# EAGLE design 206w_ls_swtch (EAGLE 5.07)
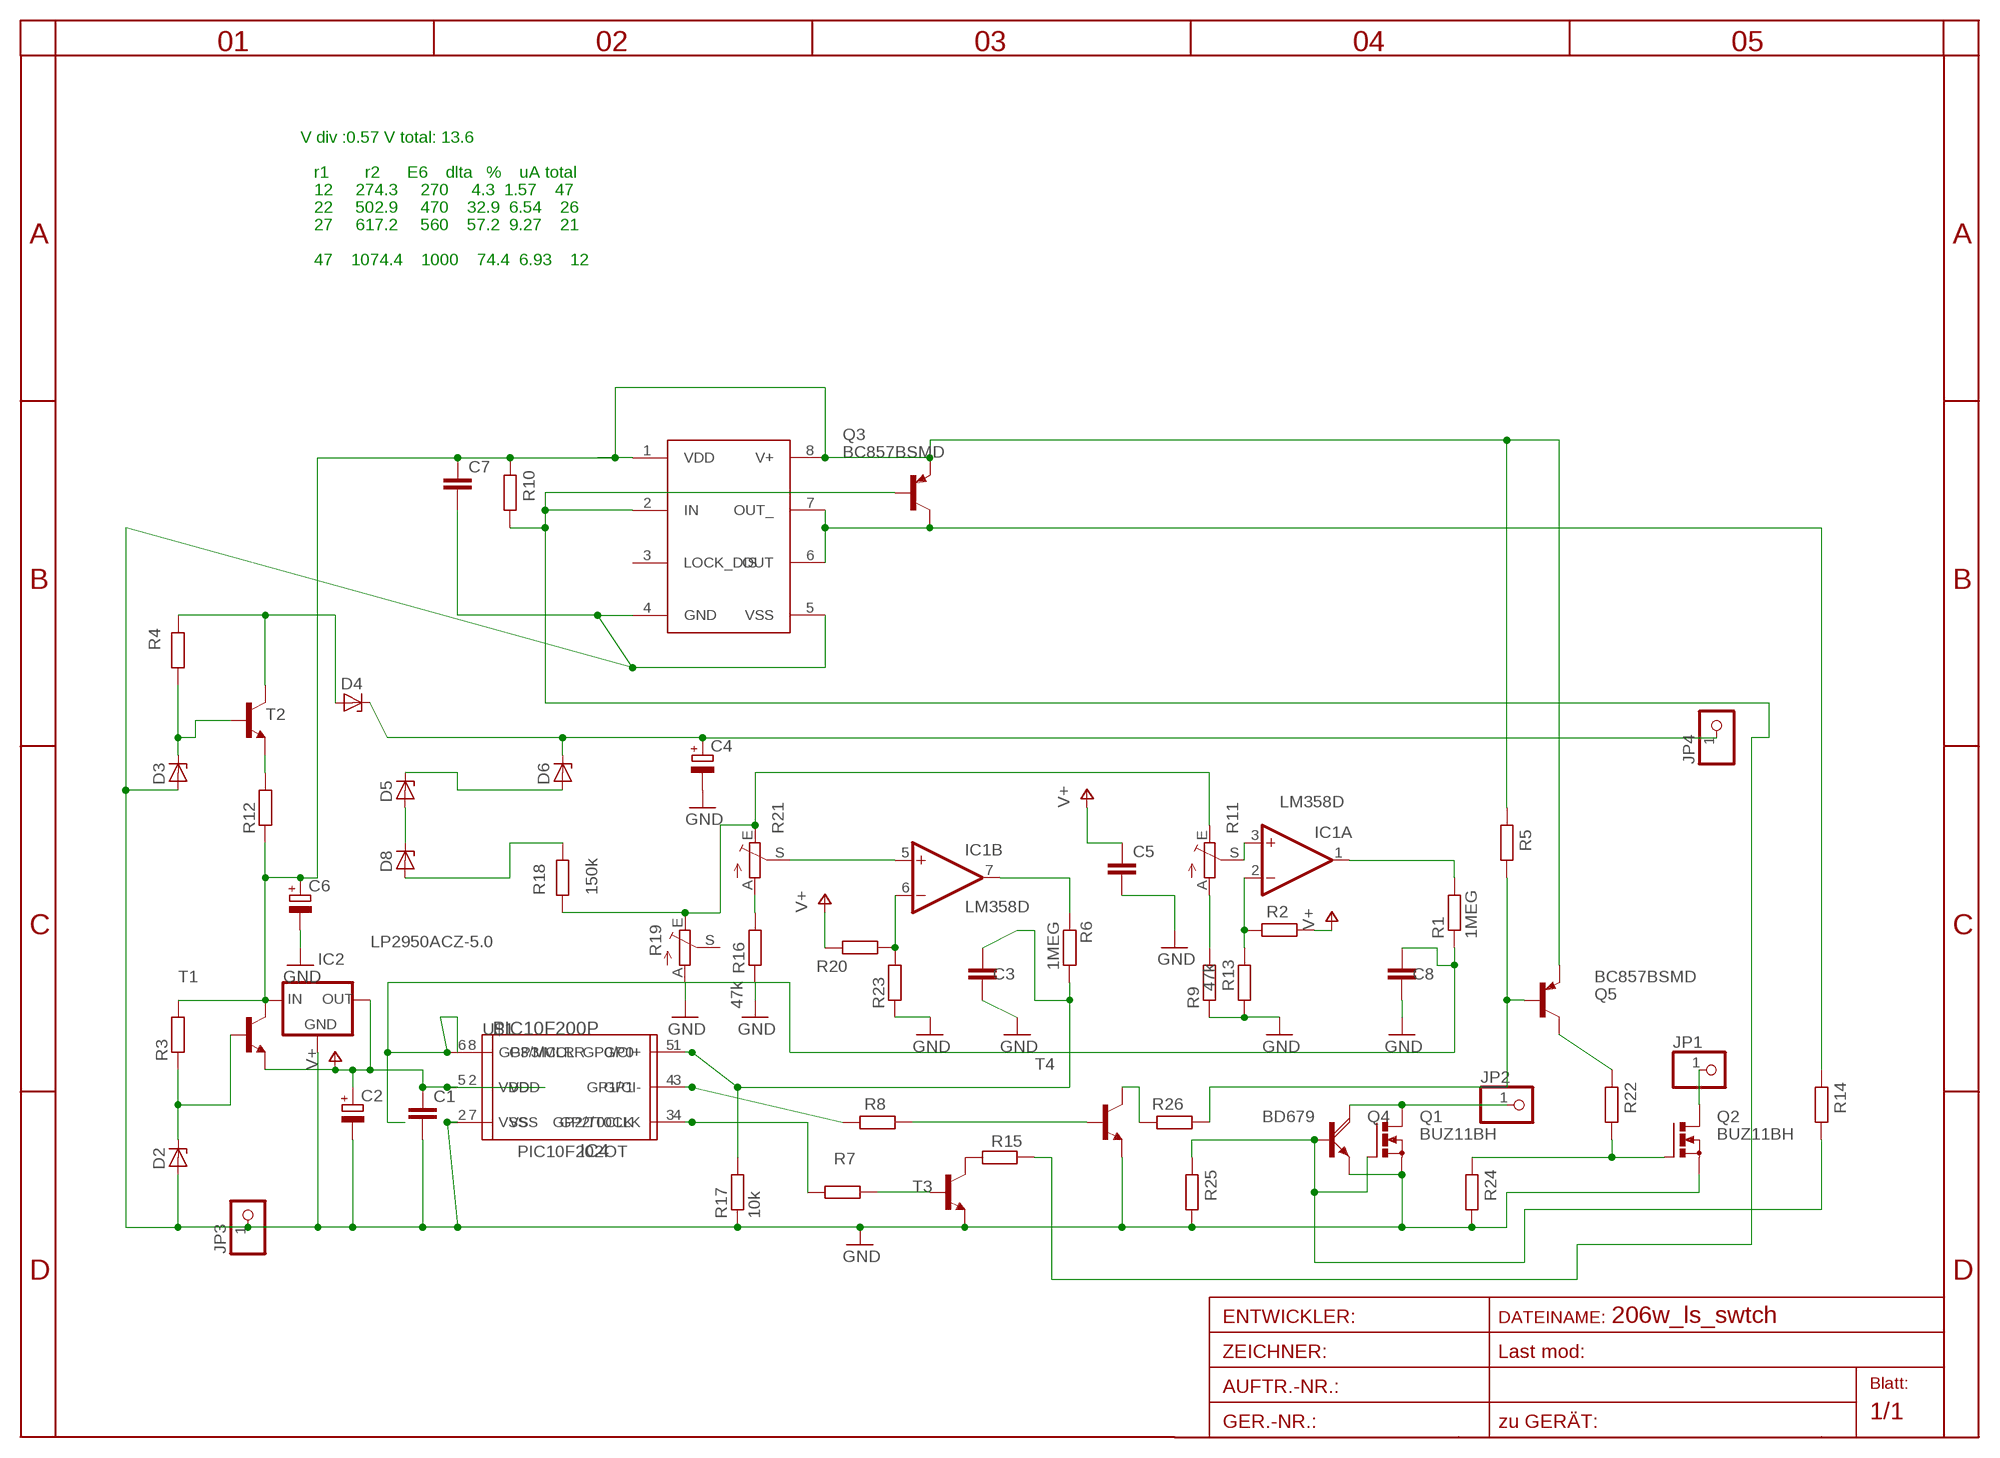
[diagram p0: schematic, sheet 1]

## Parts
C1  C-EUC1206  [C1206]
C2  CPOL-EUSANYO_SMD_E12  [SANYO-OSCON_SMD_E12]
C3  C-EUC1206  [C1206]
C4  CPOL-EUE5-8.5  [E5-8,5]
C5  C-EUC1206  [C1206]
C6  CPOL-EUSANYO_SMD_E12  [SANYO-OSCON_SMD_E12]
C7  C-EUC1206  [C1206]
C8  C-EUC1206  [C1206]
D2  ZENER-DIODESOD80C  [SOD80C]
D3  ZENER-DIODESMB  [SMB]
D4  ZENER-DIODESMB  [SMB]
D5  ZENER-DIODESMB  [SMB]
D6  ZENER-DIODESMB  [SMB]
D8  ZENER-DIODESMB  [SMB]
IC1  LM358D  [SO08]
IC2  LP2950ACZ-5.0  [TO92]
IC3  TC4432X  [SO-08]
IC4  PIC10F200P  [DIL8]
JP1  PINHD-1X11MM6  [1X1MM8]
JP2  PINHD-1X11MM6  [1X1MM8]
JP3  PINHD-1X11MM6  [1X1MM8]
JP4  PINHD-1X11MM6  [1X1MM8]
Q1  BUZ11BH  [TO220BH]
Q2  BUZ11BH  [TO220BH]
Q3  BC857BSMD  [SOT23-BEC]
Q4  BD679  [TO126AV]
Q5  BC857BSMD  [SOT23-BEC]
R1  1MEG  R-EU_R1206  [R1206]
R2  R-EU_R0805  [R0805]
R3  R-EU_R0805  [R0805]
R4  R-EU_R0805  [R0805]
R5  R-EU_R0805  [R0805]
R6  1MEG  R-EU_R1206  [R1206]
R7  R-EU_R0805  [R0805]
R8  R-EU_R0805  [R0805]
R9  47k  R-EU_R0805  [R0805]
R10  R-EU_R0805  [R0805]
R11  TRIM_EU-CA6V  [CA6V]
R12  R-EU_R0805  [R0805]
R13  R-EU_R1206  [R1206]
R14  R-EU_R0805  [R0805]
R15  R-EU_R0805  [R0805]
R16  47k  R-EU_R0805  [R0805]
R17  10k  R-EU_R0805  [R0805]
R18  150k  R-EU_R1206  [R1206]
R19  TRIM_EU-CA6V  [CA6V]
R20  R-EU_R1206  [R1206]
R21  TRIM_EU-CA6V  [CA6V]
R22  R-EU_R0805  [R0805]
R23  R-EU_R1206  [R1206]
R24  R-EU_R0805  [R0805]
R25  R-EU_R0805  [R0805]
R26  R-EU_R0805  [R0805]
T1  BC846BLT1-NPN-SOT23-BEC  [SOT23-BEC]
T2  BC846BLT1-NPN-SOT23-BEC  [SOT23-BEC]
T3  BC846BLT1-NPN-SOT23-BEC  [SOT23-BEC]
T4  BC846BLT1-NPN-SOT23-BEC  [SOT23-BEC]
U$1  PIC10F202OT  [SOT23-6]

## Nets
BB: IC3.2(IN) Q3.B R10.1 R15.2
GND: C1.2 C2.- C3.2 C4.- C5.2 C6.- C7.2 C8.2 D2.A D3.A IC2.2(GND) IC3.4(GND) IC3.5(VSS) IC4.7(VSS) JP3.1 Q1.S Q2.S Q4.E R9.1 R13.1 R16.1 R17.1 R19.A R23.1 R24.1 R25.1 T3.E T4.E U$1.2(VSS)
HOTSPOT: JP2.1 Q1.D Q4.C
N$1: IC1.5(B:+IN) R21.S
N$2: C8.1 IC4.8(GP3/MCLR) R1.1 U$1.6(GP3/MCLR)
N$3: Q1.G Q4.B R14.1 R25.2
N$4: R11.E R18.1 R19.E R21.E
N$5: R26.2 T4.C
N$6: D2.C R3.1 T1.B
N$7: R9.2 R11.A
N$8: IC1.3(A:+IN) R11.S
N$9: IC4.3(GP2/T0CLK) R7.1 U$1.4(GP2/T0CLK)
N$10: D5.C D6.A
N$11: IC3.6(OUT) IC3.7(OUT_) Q3.C R14.2
N$12: D3.C R4.1 T2.B
N$13: R8.1 T4.B
N$14: C3.1 IC4.5(GP0) R6.2 R17.2 U$1.1(GP0/CI+)
N$15: IC1.2(A:-IN) R2.2 R13.2
N$17: D5.A D8.C
N$19: D8.A R18.2
N$21: D4.A R4.2 T2.C
N$22: R12.2 T2.E
N$23: R16.2 R21.A
N$24: IC1.6(B:-IN) R20.2 R23.2
N$25: IC4.4(GP1) R8.2 U$1.3(GP1/CI-)
N$26: R7.2 T3.B
N$27: IC1.7(B:OUT) R6.1
N$28: Q5.C R22.2
N$29: Q2.G R22.1 R24.2
N$30: Q5.B R5.1 R26.1
N$31: R15.1 T3.C
N$33: IC1.1(A:OUT) R1.2
OUT2: JP1.1 Q2.D
V60: C4.+ D4.C D6.C JP4.1
V+: C1.1 C2.+ C5.1 IC2.1(OUT) IC4.2(VDD) R2.1 R20.1 T1.E U$1.5(VDD)
VCC: C6.+ C7.1 IC2.3(IN) IC3.1(VDD) IC3.8(V+) Q3.E Q5.E R3.2 R5.2 R10.2 R12.1 T1.C
Unconnected: IC3.3(LOCK_DIS) R19.S

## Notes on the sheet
- V div :0.57 V total: 13.6
- r1        r2      E6    dlta   %    uA total
- 12     274.3     270     4.3  1.57    47
- 22     502.9     470    32.9  6.54    26
- 27     617.2     560    57.2  9.27    21
- 47    1074.4    1000    74.4  6.93    12

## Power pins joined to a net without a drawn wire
GND: IC1.4(P:V-)
V+: IC1.8(P:V+)

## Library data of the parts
C1 C3 C5 C7 C8 = rcl:C-EU: CAPACITOR, European symbol
C2 C4 C6 = rcl:CPOL-EU: POLARIZED CAPACITOR, European symbol
D2-D6 D8 = diode-1:ZENER-DIODE: Z-Diode
IC1 = linear4:LM358: OP AMP
IC2 = v-reg:LP2950?*: Source: http://cache.national.com/ds/LP/LP2950.pdf
IC3 = microchip:TC4432
IC4 = microchip-5:PIC10F20*: uPC nW 0,25/0,5k Program Flash memory
JP1-JP4 = pinhead:PINHD-1X1: PIN HEADER
Q1 Q2 = transistor-power:BUZ11: N-CHANNEL MOS FET
Q3 Q5 = transistor-pnp:BC857*: PNP Transistror
Q4 = transistor-power:BD679: NPN DARLINGTON TRANSISTOR
R1-R6 R8-R10 R12 R14-R16 R20 R22 R24-R26 = rcl:R-EU_: RESISTOR, European symbol
R7 R13 R17 R18 R23 = rcl-2:R-EU_: RESISTOR, European symbol
R11 R19 R21 = pot:TRIM_EU-: POTENTIOMETER
T1-T4 = transistor-neu-to92:*-NPN-: NPN Transistror
U$1 = microchip-5:PIC10F2*: uPC nW 0,25/0,5k Program Flash memory Comparator

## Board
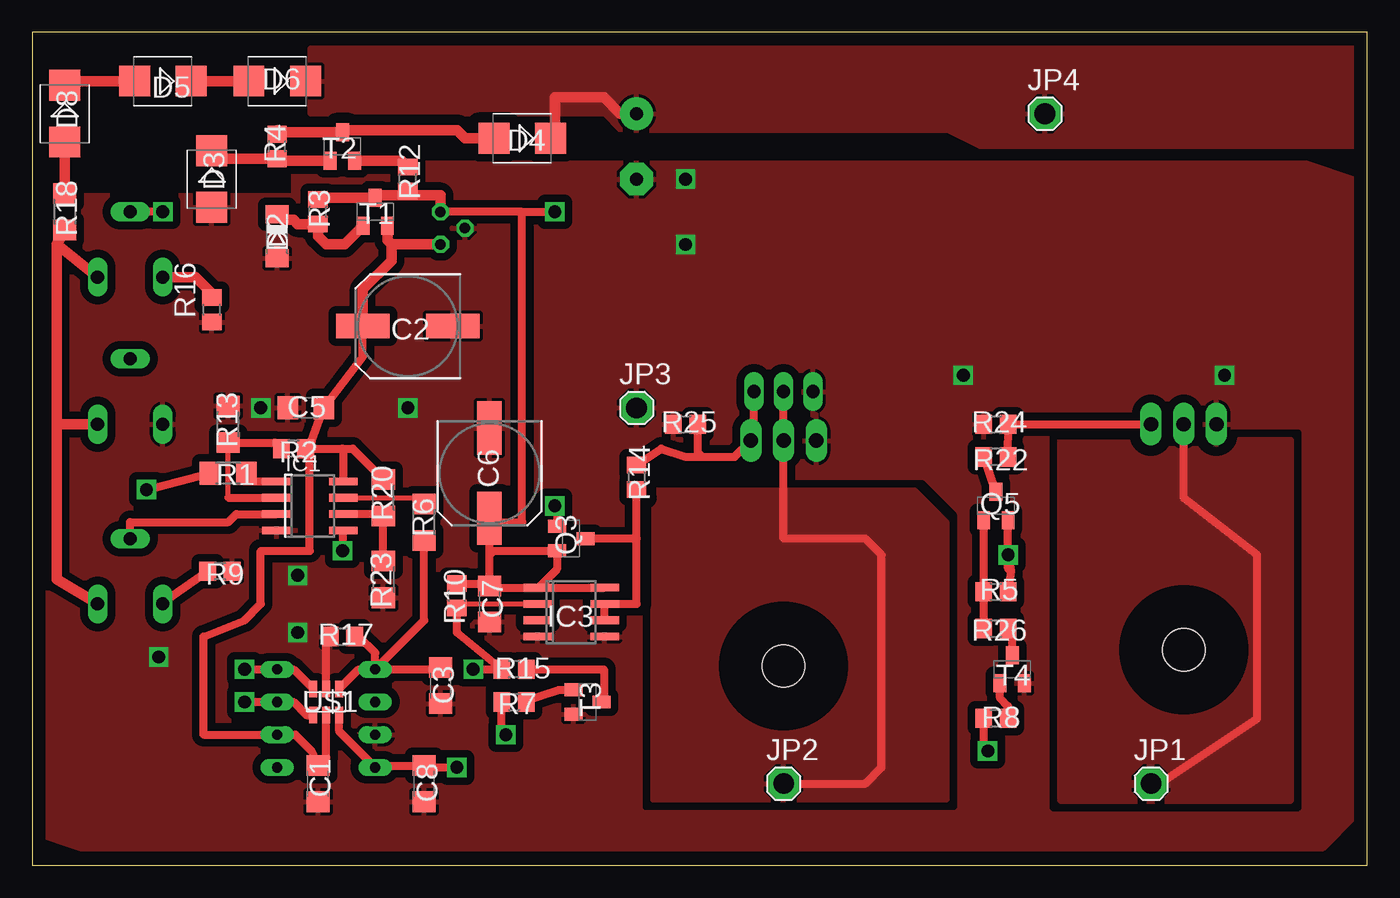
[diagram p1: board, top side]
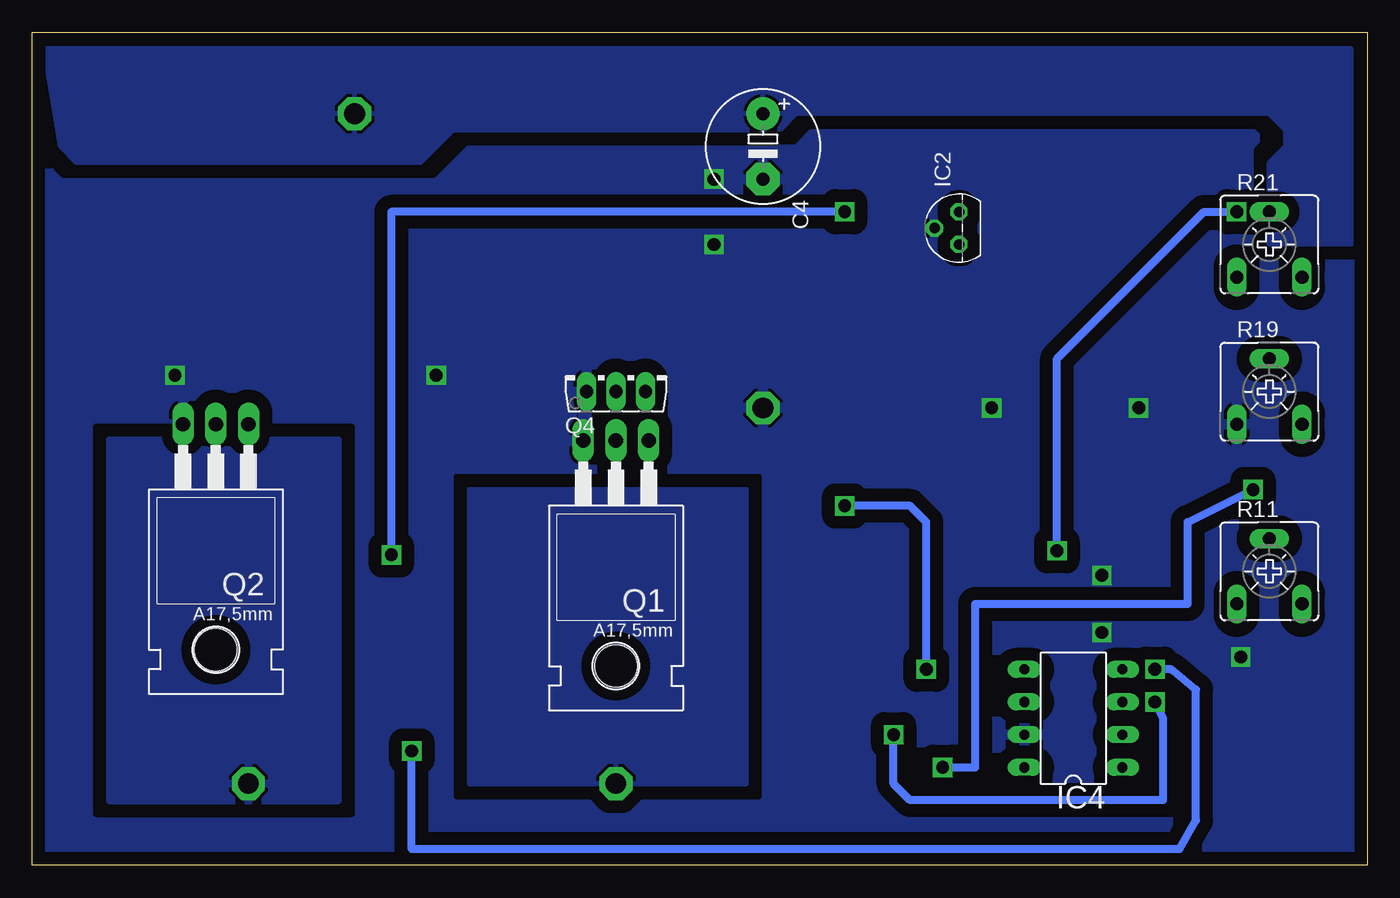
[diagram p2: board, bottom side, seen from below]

Size 103.81 x 64.76 mm. Coordinates in mm from the lower left corner, seen from the top.
Outline: 0,0 103.81,0 103.81,64.76 0,64.76 0,0
Copper layers (1*16): Top 0.035mm / dielectric 1.5mm / Bottom 0.035mm
Design rules "default": minimum track width 10mil, minimum drill 24mil, track to track 8mil, track to pad 8mil, pad to pad 8mil, via to via 8mil, smd to smd 8mil, copper to edge 40mil, drill to drill 8mil, minimum pad ring 10mil, minimum via ring 8mil, stop-mask expansion 4mil, vias tented up to drill 0mil, thermal gap 10mil

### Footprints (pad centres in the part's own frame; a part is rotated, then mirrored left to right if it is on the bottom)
C1206 = smd 1.6 x 1.8: 1 -1.4,0; 2 1.4,0
SANYO-OSCON_SMD_E12 = smd 4.15 x 1.9: + 3.5,0; - -3.5,0
E5-8,5 = drill 1.016 pad 2.54 round: + -2.54,0 | drill 1.016 pad 2.54 octagon: - 2.54,0
SOD80C = smd 1.4 x 1.8: A 1.7,0; C -1.7,0
SMB = smd 2.4 x 2.4: A 2.2,0; C -2.2,0
SO08 = smd 0.6 x 2.2: 1 -1.905,-2.6; 2 -0.635,-2.6; 3 0.635,-2.6; 4 1.905,-2.6; 5 1.905,2.6; 6 0.635,2.6; 7 -0.635,2.6; 8 -1.905,2.6
TO92 = drill 0.813 octagon: 1 -1.27,0; 2 0,1.905; 3 1.27,0
SO-08 = smd 0.6 x 2.2: 1 -1.905,-2.6; 2 -0.635,-2.6; 3 0.635,-2.6; 4 1.905,-2.6; 5 1.905,2.6; 6 0.635,2.6; 7 -0.635,2.6; 8 -1.905,2.6
DIL8 = drill 0.8 long: 1 -3.81,-3.81; 2 -1.27,-3.81; 3 1.27,-3.81; 4 3.81,-3.81; 5 3.81,3.81; 6 1.27,3.81; 7 -1.27,3.81; 8 -3.81,3.81
1X1MM8 = drill 1.6 pad 2.54 octagon: 1 0,0
TO220BH = drill 1.118 long: D 0,-6.35; G -2.54,-6.35; S 2.54,-6.35 | hole 3.302: 0,11.176
SOT23-BEC = smd 1 x 1.4: B -0.95,-1.1; C 0,1.1; E 0.95,-1.1
TO126AV = drill 1.016 long: B 2.286,-1.27; C 0,-1.27; E -2.286,-1.27
R1206 = smd 1.6 x 1.803: 1 -1.422,0; 2 1.422,0
R0805 = smd 1.3 x 1.5: 1 -0.95,0; 2 0.95,0
CA6V = drill 1.016 long: A -2.54,-2.54; E 2.54,-2.54; S 0,2.54
SOT23-6 = smd 0.635 x 1.27: 1 -1.016,-1.016; 2 0,-1.016; 3 1.016,-1.016; 4 1.016,1.016; 5 0,1.016; 6 -1.016,1.016

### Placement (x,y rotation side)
C1  22.23,6.35 270 top
C2  29.21,41.91 180 top
C3  31.75,13.97 270 top
C4  46.99,55.88 270 bottom
C5  21.27,35.56 180 top
C6  35.56,30.48 270 top
C7  35.56,20.32 270 top
C8  30.48,6.35 270 top
D2  19.05,48.9 270 top
D3  13.97,53.34 270 top
D4  38.1,56.52 180 top
D5  10.16,60.96 180 top
D6  19.05,60.96 180 top
D8  2.54,58.42 270 top
IC1  21.59,27.94 270 top
IC2  31.75,49.53 90 bottom
IC3  41.91,19.68 270 top
IC4  22.86,11.43 90 bottom
JP1  87,6.35 0 top
JP2  58.42,6.35 0 top
JP3  46.99,35.56 0 top
JP4  78.74,58.42 0 top
Q1  58.42,26.67 180 bottom
Q2  89.53,27.94 180 bottom
Q3  41.91,25.4 270 top
Q4  58.42,38.1 0 bottom
Q5  74.93,27.94 0 top
R1  15.24,30.48 0 top
R2  20.32,32.38 180 top
R3  22.23,50.8 90 top
R4  19.05,55.88 90 top
R5  74.93,21.27 0 top
R6  30.48,26.67 270 top
R7  37.47,12.7 0 top
R8  74.93,11.43 180 top
R9  14.61,22.86 180 top
R10  33.02,20.95 90 top
R11  7.62,22.86 0 bottom
R12  29.21,53.34 90 top
R13  15.24,34.29 270 top
R14  46.99,30.16 270 top
R15  37.47,15.24 180 top
R16  13.97,43.18 90 top
R17  24.13,17.78 0 top
R18  2.54,50.8 90 top
R19  7.62,36.83 0 bottom
R20  27.3,28.57 270 top
R21  7.62,48.26 0 bottom
R22  74.93,31.75 180 top
R23  27.3,22.23 90 top
R24  74.93,34.29 0 top
R25  50.8,34.29 0 top
R26  74.93,18.41 0 top
T1  26.67,50.8 0 top
T2  24.13,55.88 0 top
T3  43.18,12.7 270 top
T4  76.2,15.24 0 top
U$1  22.86,12.7 180 top

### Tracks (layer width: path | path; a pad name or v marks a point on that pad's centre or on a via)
BB  (via drill 1)
  Top 0.406: 33.34,20.32 IC3.2
  Top 0.61: 33.34,20.32 R10.1 33.02,18.1 R15.2 v34.29,15.24 | Q3.B 40.81,27.77 v40.64,27.94
  Bottom 0.61: v40.64,27.94 35.56,27.94 34.29,26.67 v34.29,15.24
GND  (via drill 1)
  Top 0.61: U$1.2 22.86,17.46 R17.1
  other vias: 20.64,18.1 29.21,35.56 20.64,22.54 9.84,16.19 50.8,48.26 50.8,53.34 92.71,38.1 72.39,38.1 17.78,35.56
  pour Bottom (isolate 1.016, rank 5): 102.87,60.96 102.87,0 90.17,0 1.27,1.27 1.27,53.34 1.27,58.42
  pour Top (isolate 0.61, rank 5): 1.27,52.07 20.32,52.07 20.32,54.61 99.06,54.61 102.87,53.34 102.87,3.81 100.33,1.27 3.81,1.27 0,2.54
HOTSPOT
  Top 0.61: JP2.1 64.77,6.35 66.04,7.62 66.04,24.13 64.77,25.4 58.42,25.4 Q1.D Q4.C
  pour Top (isolate 0.813, rank 3): 48.26,29.21 68.58,29.21 71.12,26.67 71.12,5.08 48.26,5.08
  pour Bottom (isolate 0.813, rank 3): 48.26,29.21 69.85,29.21 69.85,6.35 48.26,6.35
N$1  (via drill 1)
  Top 0.61: IC1.5 24.19,24.19 v24.13,24.45 | v10.16,50.8 R21.S
  Bottom 0.61: v24.13,24.45 24.13,39.37 12.7,50.8 v10.16,50.8
N$2  (via drill 1)
  Top 0.61: U$1.6 23.88,10.41 IC4.8 26.8,7.75 C8.1 30.61,7.62 v33.02,7.62 | v8.89,29.21 R1.1
  Bottom 0.61: v8.89,29.21 13.97,26.67 13.97,20.32 30.48,20.32 30.48,7.62 v33.02,7.62
N$3
  Top 0.61: R14.1 48.9,32.38 50.8,31.75 52.07,31.75 | 52.07,31.75 54.61,31.75 Q1.G 56.13,33.27 Q4.B | R25.2 51.75,32.07 52.07,31.75
N$4
  Top 0.813: 1.91,48.26 R18.1 | 1.91,48.26 R21.E | 1.91,34.29 1.91,48.26 | 1.91,34.29 R19.E | 1.91,34.29 1.91,22.23 R11.E
N$5
  Top 0.61: T4.C 76.2,18.09 R26.2
N$6
  Top 0.813: T1.B 24.28,48.26 22.86,48.26 22.23,48.9 R3.1 20.64,49.85 20.32,50.16 19.48,50.16 D2.C
N$7
  Top 0.61: R9.2 10.47,20.64 R11.A
N$8
  Top 0.61: IC1.3 15.88,27.3 15.24,26.67 7.62,26.67 R11.S
N$9  (via drill 1)
  Top 0.61: U$1.4 21.34,11.68 20.32,12.7 IC4.3 v16.51,12.7 | R7.1 36.52,10.47 v36.83,10.16
  Bottom 0.61: v36.83,10.16 36.83,6.35 35.56,5.08 15.88,5.08 15.88,11.43 v16.51,12.7
N$10
  Top 0.813: D5.C D6.A
N$11
  Top 0.61: Q3.C 46.99,25.4 46.99,20.32 | IC3.6 IC3.7 46.99,20.32 | 46.99,20.32 R14.2
N$12
  Top 0.813: T2.B 19.2,54.78 R4.1 14.58,54.93 D3.C
N$13
  Top 0.61: R8.1 75.88,12.38 75.25,13.02 T4.B
N$14
  Top 0.61: U$1.1 25.4,15.24 IC4.5 | R17.2 25.4,17.78 26.67,16.51 IC4.5 | IC4.5 31.62,15.24 C3.1 | R6.2 30.48,19.05 IC4.5
N$15
  Top 0.406: 15.24,28.57 R13.2
  Top 0.61: R13.2 18.89,32.87 R2.2 | 15.24,28.57 IC1.2
N$17
  Top 0.813: D5.A 2.54,60.96 D8.C
N$19
  Top 0.813: R18.2 D8.A
N$21
  Top 0.813: D4.A 33.66,56.52 33.02,57.15 24.3,57.15 T2.C 19.22,56.98 19.05,57.15 R4.2
N$22
  Top 0.813: T2.E 28.72,54.78 R12.2
N$23
  Top 0.813: R21.A 12.7,45.72 13.97,44.45 R16.2
N$24
  Top 0.61: IC1.6 27.15,27.3 R20.2 R23.2
N$25  (via drill 1)
  Top 0.61: U$1.3 20.32,15.24 IC4.4 v16.51,15.24 | R8.2 73.98,9.21 v74.3,8.89
  Bottom 0.61: v74.3,8.89 74.3,1.27 14.61,1.27 13.34,3.49 13.34,13.65 15.24,15.24 v16.51,15.24
N$26
  Top 0.61: T3.B 40.95,13.65 38.1,12.7 38.1,12.38 R7.2
N$27
  Top 0.406: IC1.7 30,28.57
  Top 0.61: 30,28.57 R6.1
N$28
  Top 0.61: Q5.C R22.2
N$29
  Top 0.61: R24.2 Q2.G | R22.1 R24.2 | R24.2
N$30
  Top 0.61: R26.1 R5.1 Q5.B
N$31
  Top 0.61: R15.1 44.45,15.24 44.45,12.87 T3.C
N$33
  Top 0.61: R1.2 16.51,29.84 IC1.1 19.62,29.84
OUT2
  Top 0.61: Q2.D 89.53,28.57 95.25,24.13 95.25,11.43 87.63,6.35 JP1.1 86.36,6.35
  pour Top (isolate 0.813): 80.01,33.02 97.79,33.02 97.79,5.08 80.01,5.08
  pour Bottom (isolate 0.813): 80.01,33.02 97.79,33.02 97.79,5.08 80.01,5.08
V60
  Top 0.813: C4.+ 45.72,58.42 44.45,59.69 40.64,59.69 40.64,56.85 D4.C
  pour Top (isolate 0.813, rank 4): 102.87,63.5 21.59,63.5 21.59,58.42 44.45,58.42 45.72,57.15 71.12,57.15 73.66,55.88 102.87,55.88
  pour Bottom (isolate 0.813, rank 4): 102.87,63.5 1.27,63.5 1.27,48.26 7.62,48.26 7.62,54.61 6.35,55.88 6.35,57.15 7.62,58.42 44.45,58.42 45.72,57.15 71.12,57.15 73.66,54.61 100.33,54.61 101.6,55.88
V+
  Top 0.61: U$1.5 22.86,8.38 C1.1 21.72,8.89 20.45,10.16 IC4.2 13.34,10.16 13.34,17.78 16.51,19.05 17.78,20.32 17.78,24.45 21.59,24.45 21.59,32.89 21.72,33.02 | C2.+ 25.71,39.55 C5.1 21.72,33.02 | 21.72,33.02 21.72,32.84 R2.1 24.13,32.38 | 24.13,32.38 24.92,32.38 R20.1 | IC1.8 24.19,32.33 24.13,32.38
  Top 0.813: T1.E 27.62,48.58 27.94,48.26 | 27.94,48.26 IC2.1 | C2.+ 25.71,44.76 27.94,46.99 27.94,48.26
VCC  (via drill 1)
  Top 0.61: 38.1,50.8 IC2.3 | 38.1,50.8 38.1,26.67 35.87,26.67 C6.+ 35.56,24.13 | R10.2 35.38,21.91 C7.1 | C7.1 35.56,24.13 | C7.1 35.69,21.59 IC3.1 IC3.8 | 35.56,24.13 35.88,24.45 Q3.E 40.81,23.03 39.37,21.59 | v75.88,24.13 76.1,22.88 | 76.1,22.88 R5.2 | 38.1,50.8 v40.64,50.8 | Q5.E 75.88,23.09 76.1,22.88
  Top 0.813: 29.21,52.07 R12.1 | 29.21,52.07 26.84,52.07 T1.C 22.38,51.9 R3.2 | 29.21,52.07 31.75,52.07 IC2.3
  Bottom 0.61: v75.88,24.13 75.88,50.8 v40.64,50.8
